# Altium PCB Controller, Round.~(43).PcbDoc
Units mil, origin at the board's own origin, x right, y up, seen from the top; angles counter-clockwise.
Board outline 1800 x 1800 mil, 4 copper layers (Top Layer, MidLayer1, MidLayer2, Bottom Layer); 55 components, 57 nets, 233 pads, 111 vias.
Unrouted connection lines stored in the file: 24.
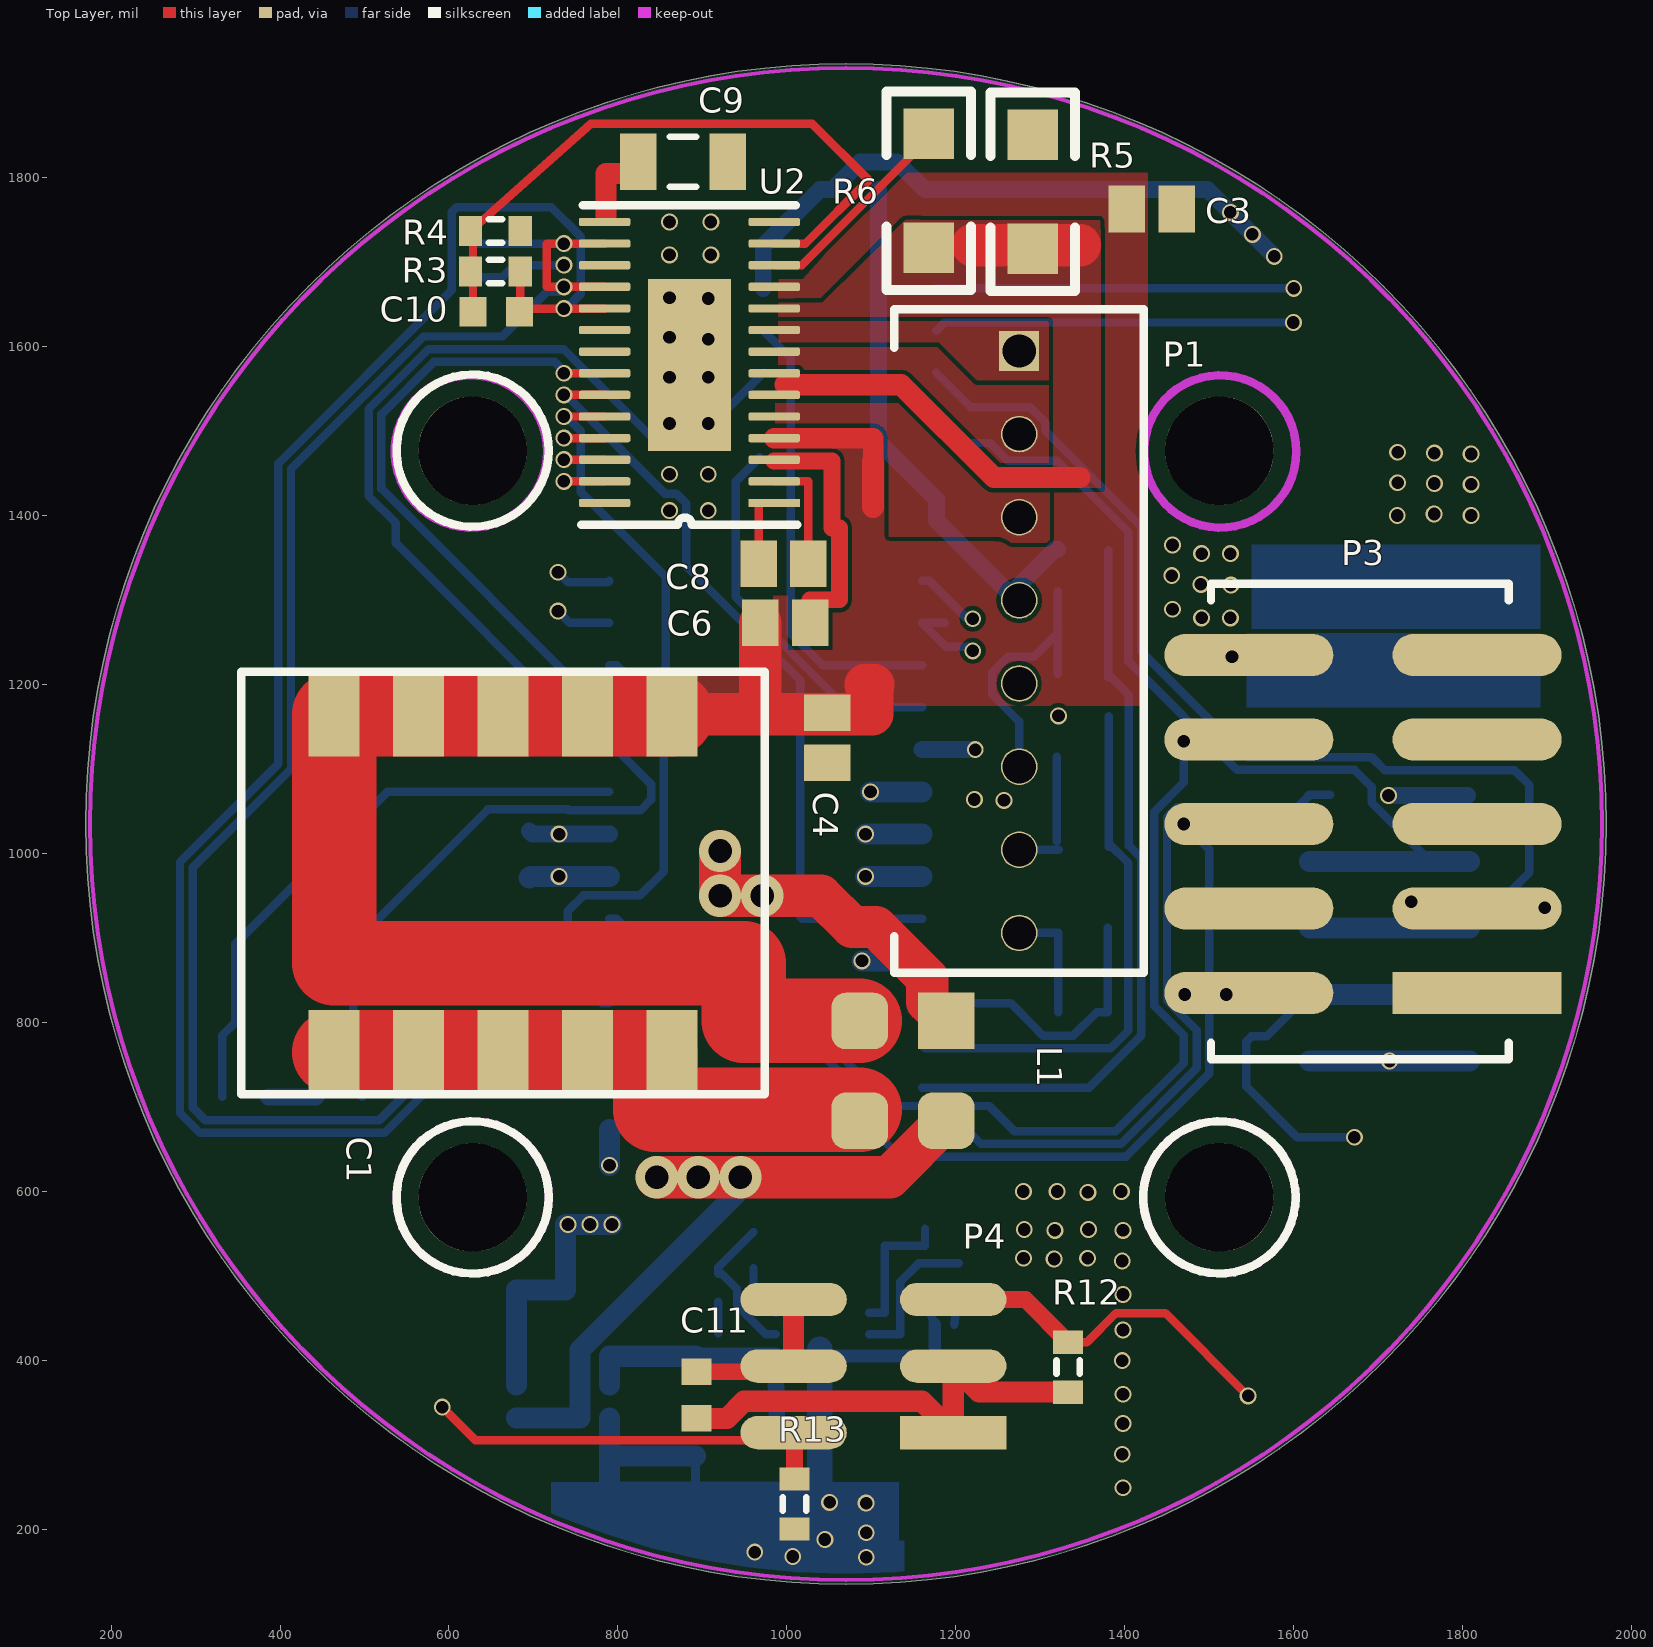
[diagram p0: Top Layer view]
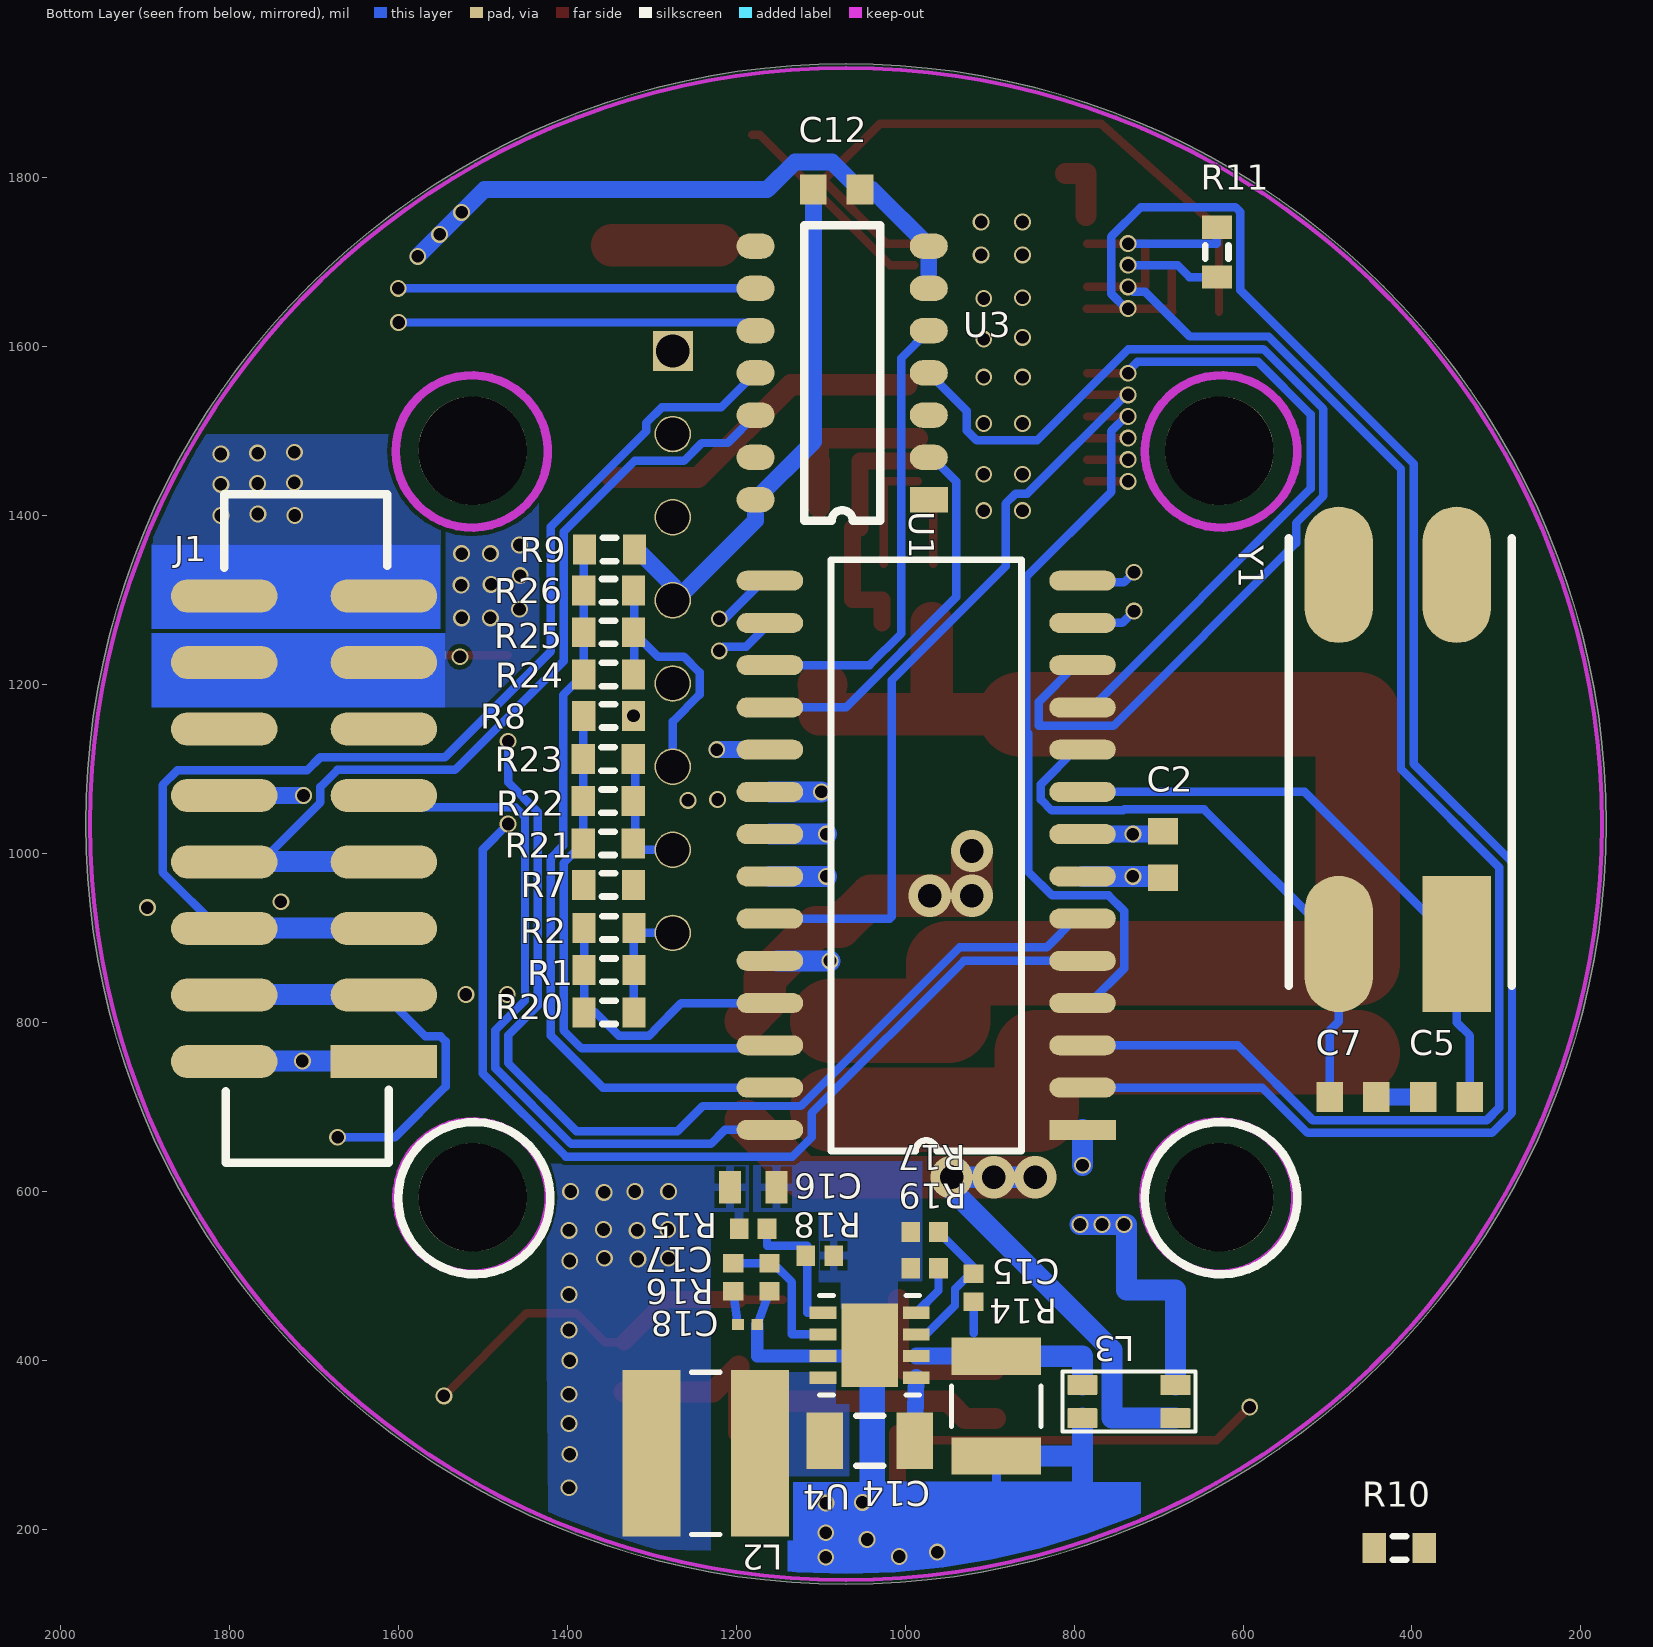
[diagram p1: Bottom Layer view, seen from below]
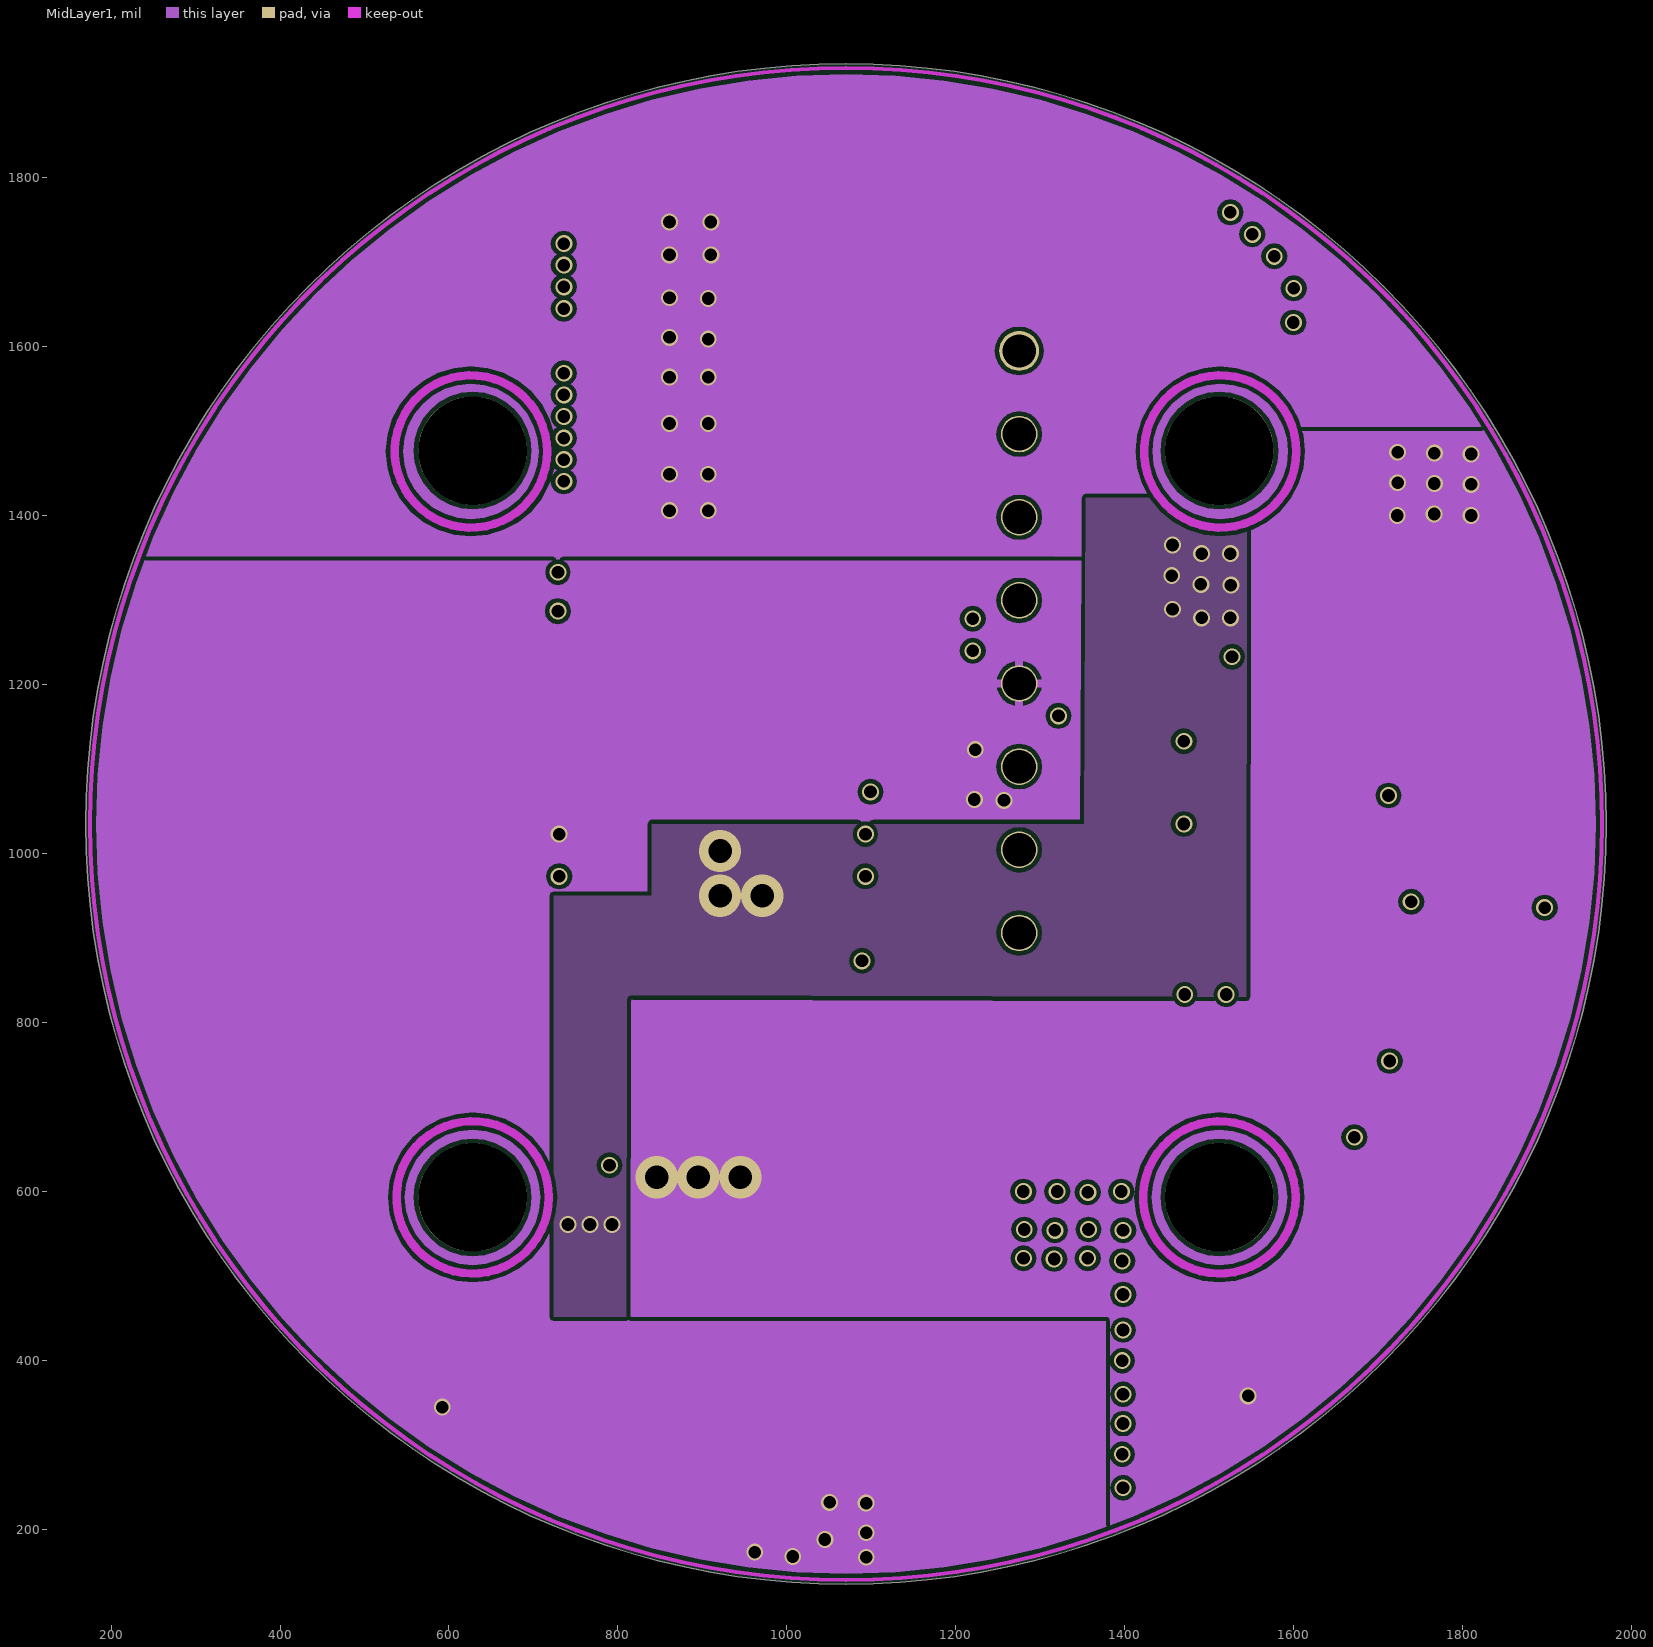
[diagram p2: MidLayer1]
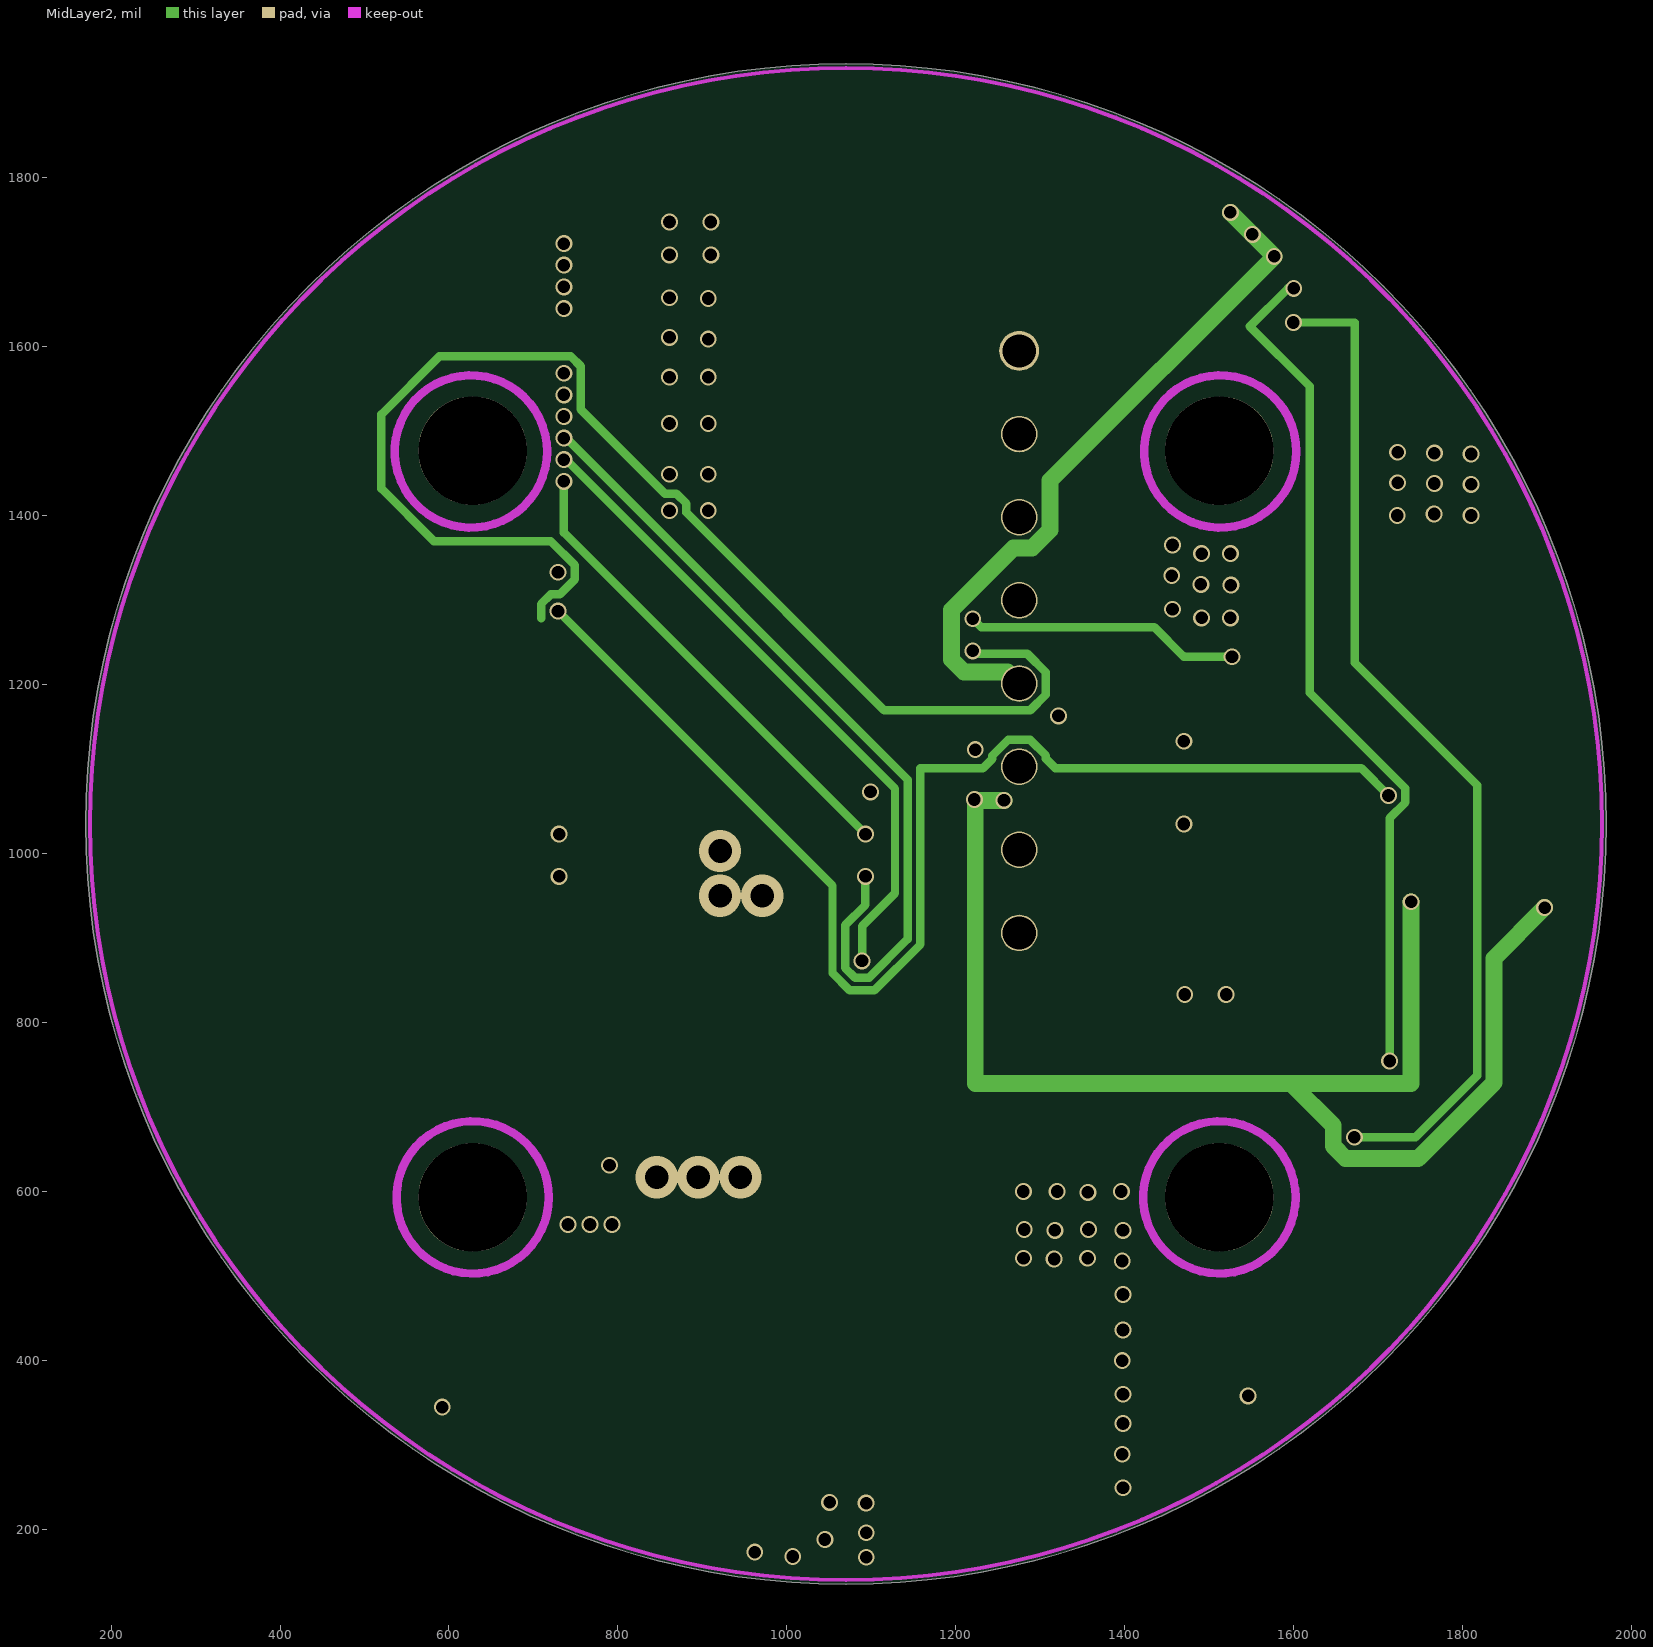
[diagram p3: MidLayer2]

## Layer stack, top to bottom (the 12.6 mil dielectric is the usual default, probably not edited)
Top Layer: signal copper 1.4
Dielectric: core 12.6, FR-4, Dk 4.8
MidLayer1: signal copper 1.4
Dielectric: prepreg 12.6, FR-4, Dk 4.8
MidLayer2: signal copper 1.4
Dielectric: core 12.6, FR-4, Dk 4.8
Bottom Layer: signal copper 1.4

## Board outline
1070,135 cw(c1070,1035) 170,1035 cw(c1070,1035) 1070,1935 cw(c1070,1035) 1970,1035 cw(c1070,1035)

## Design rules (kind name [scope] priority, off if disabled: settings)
Clearance [All] p1: gap=5
HoleSize [All] p1: absolutevalues=TRUE maxlimit=130 minlimit=15 maxpercent=80.000 minpercent=20.000
MinimumSolderMaskSliver [All] p1: minsoldermaskwidth=5
PolygonConnect PolygonConnect_Via [IsVia] p1: connectstyle=Direct reliefconductorwidth=10 reliefentries=4 polygonreliefangle="90 Angle"
PolygonConnect PolygonConnect_7 [InComponent('U2') vs InNet('GND')] p2: connectstyle=Relief reliefconductorwidth=10 reliefentries=4 polygonreliefangle="90 Angle"
PolygonConnect PolygonConnect_6 [InComponent('L1') vs InNet('GND')] p3: connectstyle=NoConnect reliefconductorwidth=10 reliefentries=4 polygonreliefangle="90 Angle"
PolygonConnect PolygonConnect_5 [InComponent('L2') vs InNet('VCC')] p4: connectstyle=Direct reliefconductorwidth=10 reliefentries=4 polygonreliefangle="90 Angle"
PolygonConnect PolygonConnect_4 [(InComponent('R19') OR InComponent('R17') OR InComponent('U4')) vs InNet('SGND')] p5: connectstyle=Direct reliefconductorwidth=10 reliefentries=4 polygonreliefangle="90 Angle"
PolygonConnect PolygonConnect_3 [All vs InNet('NetC14_1')] p6: connectstyle=Direct reliefconductorwidth=10 reliefentries=4 polygonreliefangle="90 Angle"
PolygonConnect PolygonConnect_2 [InComponent('C4')] p7: connectstyle=Relief reliefconductorwidth=10 reliefentries=4 polygonreliefangle="90 Angle"
PolygonConnect PolygonConnect_1 [(InComponent('C1')) vs InNet('GND')] p8: connectstyle=NoConnect reliefconductorwidth=10 reliefentries=4 polygonreliefangle="90 Angle"
PolygonConnect [(InNet('NetP1_1') OR InNet('NetP1_2') OR InNet('NetP1_3') OR InNet('VM') OR InNet('VSENSE')) vs (InNet('NetP1_1') OR InNet('NetP1_2') OR InNet('NetP1_3') OR InNet('VM') OR InNet('VSENSE'))] p9: connectstyle=Direct reliefconductorwidth=10 reliefentries=4 polygonreliefangle="90 Angle"
RoomDefinition Controller [InComponentClass('Controller')] p1 off: confinementstyle=ConfineIn formatcopy=TRUE lockcomponents=FALSE outline -1845,-1985 155,-1985 155,-985 -1845,-985
RoutingVias RoutingVias_1 [(InNet('ADDR_IN') OR InNet('ADDR_OUT'))] p1: holewidth=15 width=20 viastyle="Through Hole" minholewidth=15 minwidth=20 maxholewidth=15 maxwidth=20
RoutingVias [All] p2: holewidth=15 width=20 viastyle="Through Hole" minholewidth=15 minwidth=20 maxholewidth=28 maxwidth=50
SilkscreenOverComponentPads [All] p1: minsilkscreentomaskgap=10
SolderMaskExpansion [All] p1: expansion=4
Width Width_1 [All] p1: maxlimit=100 minlimit=6 preferedwidth=10
Width [InNet('VM')] p2: maxlimit=100 minlimit=20 preferedwidth=40
25 further rules are at their usual default settings.

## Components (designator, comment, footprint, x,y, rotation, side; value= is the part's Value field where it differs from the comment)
C1 "Cap Pol1" CAPSTICK-CS4-5-SMD 464,1165 r0 top
C2 "Cap Semi" 1608[0603] 695,999 r90 bottom
C3 "Cap Semi" C0805 1432,1763 r180 top
C4 "Cap Semi" C0805 1048,1137 r90 top
C5 "Cap Semi" 1608[0603] 359,712 r180 bottom
C6 "Cap Semi" C0805 998,1273 r180 top
C7 "Cap Semi" 1608[0603] 470,712 r0 bottom
C8 "Cap Semi" C0805 996,1343 r180 top
C9 "Cap Semi" C1206 877,1819 r180 top
C10 "Cap Semi" 1608[0603] 656,1641.38 r180 top locked
C11 "Cap Semi" 1608[0603] 893,359 r270 top
C12 "Cap Semi" 1608[0603] 1081,1786 r180 bottom
C14 "C1005X7R1E103K" C1206 1042,305 r180 bottom
C15 "C3225X7R2A225K230AB" 1210 892,346 r270 bottom
C16 "C1608X5R0J106M" 0603 1180,605 r180 bottom
C17 "C0402C330J5GAC" 0402 1160.5,498.5 r270 bottom
C18 "GRM033R61A472KA01D" 0201 1186.5,442.5 r180 bottom
J1 "M80-8281642" M80-828XXXXDIL 1806,1305 r180 bottom
L1 "DLW5BTM501SQ2" DLW5A_5B 1086.3,801.85 r0 top locked
L2 "LPS5030-823MLB" LPS5030 1236,290 r180 bottom
L3 "SRF3216-222Y" SRF3216 680,371 r270 bottom
P1 "MKS 1658-6-0-808" MKS_1658_A_KF 1275,1595 r270 top locked
P3 "N2510-6V0C-RB-WD" N2510_SMD 1817,835 r180 top
P4 "M80-8280642" M8082806DIL 1008,472 r0 top locked
R1 "Res3" J1-0603 1350.53,912 r0 bottom
R2 "Res3" J1-0603 1350.53,862 r0 bottom
R3 "Res3" J1-0603 655,1689 r0 top locked
R4 "Res3" J1-0603 655,1737 r180 top locked
R5 "Res3" 1206 1291,1851 r270 top locked
R6 "Res3" 1206 1168,1717 r90 top locked
R7 "Res3" J1-0603 1351,963 r180 bottom
R8 "Res3" J1-0603 1351,1163 r180 bottom
R9 "Res3" J1-0603 1350,1360 r180 bottom
R10 "Res3" J1-0603 415,178 r180 bottom
R11 "Res3" J1-0603 631,1712 r90 bottom
R12 "Res3" J1-0603 1333,392 r90 top
R13 "Res3" J1-0603 1009,230 r90 top
R14 "CRCW0402665KFKED" 0402 919,486 r90 bottom
R15 "CRCW040253K6FKED" 0402 1180,556 r180 bottom
R16 "CRCW040246K4FKED" 0402 1203.5,498.5 r90 bottom
R17 "CRCW040242K2FKED" 0402 977,552 r0 bottom
R18 "CRCW040210K0FKED" 0402 1101,524 r180 bottom
R19 "CRCW040280K6FKED" 0402 977,509 r0 bottom
R20 "Res3" J1-0603 1350.53,812 r0 bottom
R21 "Res3" J1-0603 1351.53,1012 r0 bottom
R22 "Res3" J1-0603 1351.53,1062 r0 bottom
R23 "Res3" J1-0603 1351.53,1112 r0 bottom
R24 "Res3" J1-0603 1351,1212 r0 bottom
R25 "Res3" J1-0603 1351,1262 r0 bottom
R26 "Res3" J1-0603 1351,1311.3 r0 bottom
U1 "PIC_SERVO_SC" SOP28 790,673 r0 bottom
U2 "DRV8313" HTSSOP28 985,1415 r180 top locked
U3 "LTC2864xSOP" SOP14 972,1419 r0 bottom
U4 "TPS54061DRBR" S-PVSON-N8 1042,418 r0 bottom
Y1 "MA-506 10.0000M-C0" MA506 347,893 r0 bottom

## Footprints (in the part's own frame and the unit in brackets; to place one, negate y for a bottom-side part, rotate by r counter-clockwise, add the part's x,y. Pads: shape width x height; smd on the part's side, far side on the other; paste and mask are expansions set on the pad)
0201 [mil]
  rect 14x13 smd: 1(-11.5,0) 2(11.5,0)
0402 [mil]
  rect 22x24 smd: 1(-16.5,0) 2(16.5,0)
0603 [mil]
  rect 26x38 smd: 1(-27.5,0) 2(27.5,0)
1206 [mil]
  rect 60x60 smd: 1(0,0) 2(135,0)
  silkscreen extent -50,-50 185,50
1210 [mil]
  rect 44x106 smd: 1(-59,0) 2(59,0)
  silkscreen extent -24,-53 24,53
1608[0603] [mm] "Chip Capacitor, Body 1.6x0.8mm, IPC High Density"
  rect 0.8x0.9 smd: 1(-0.7,0) 2(0.7,0)
  body extent -0.87,-0.48 0.87,0.48, height 1.3
C0805 [mm] "Chip Capacitor, Body 2.0x1.3mm, IPC High Density"
  rect 1.1x1.4 smd: 1(-0.75,0) 2(0.75,0)
  body extent -1.1,-0.72 1.1,0.72, height 1.4
C1206 [mm] "Chip Capacitor, Body 3.2x1.6mm, IPC High Density"
  rect 1.1x1.7 smd: 1(-1.35,0) 2(1.35,0)
  silkscreen extent -0.4,-0.75 0.4,0.75, body extent -1.7,-0.9 1.7,0.9, height 1.3
CAPSTICK-CS4-5-SMD [mil]
  rect 60x100 smd: 1(0,0) 1(100,0) 1(200,0) 1(300,0) 1(400,0) 2(0,-400) 2(100,-400) 2(200,-400) 2(300,-400) 2(400,-400)
  silkscreen extent -110,-450 510,50
DLW5A_5B [mm]
  rect 1.7x1.7 smd: 1(2.6,0)
  rrect50% 1.7x1.7 smd: 2(0,0) 3(0,-3) 4(2.6,-3)
HTSSOP28 [mm] "HTTSSOP 28 Pin Package, TI"
  rect 1.55x0.25 smd: 1(0,0)
  rrect50% 1.55x0.25 smd: 2(0,-0.65) 3(0,-1.3) 4(0,-1.95) 5(0,-2.6) 6(0,-3.25) 7(0,-3.9) 8(0,-4.55) 9(0,-5.2) 10(0,-5.85) 11(0,-6.5) 12(0,-7.15) 13(0,-7.8) 14(0,-8.45) 15(5.1,-8.45) 16(5.1,-7.8) 17(5.1,-7.15) 18(5.1,-6.5) 19(5.1,-5.85) 20(5.1,-5.2) 21(5.1,-4.55) 22(5.1,-3.9) 23(5.1,-3.25) 24(5.1,-2.6) 25(5.1,-1.95) 26(5.1,-1.3) 27(5.1,-0.65) 28(5.1,0)
  rect 2.5x5.18 smd: Pad(2.55,-4.15)
  silkscreen extent -0.7,-8.95 5.8,0.65
J1-0603 [mm] "Chip Resistor, Body 1.6x0.8mm, IPC High Density"
  rect 0.7x0.9 smd: 1(-0.75,0) 2(0.75,0)
  silkscreen extent -0.2,-0.35 0.2,0.35, body extent -0.85,-0.48 0.85,0.48, height 0.9
LPS5030 [mil]
  rect 68.5x197 smd: 1(-64.25,0) 2(64.25,0)
  silkscreen extent -17,-96 17,96
M80-828XXXXDIL [mm]
  rect 3.2x1 smd: 1(4.8,-14)
  oval 3.2x1 smd: 2(0,-14) 3(4.8,-12) 4(0,-12) 5(4.8,-10) 6(0,-10) 7(4.8,-8) 8(0,-8) 9(4.8,-6) 10(0,-6) 11(4.8,-4) 12(0,-4) 13(4.8,-2) 14(0,-2) 15(4.8,0) 16(0,0)
  silkscreen extent 0,-17.05 4.95,3.05
M8082806DIL [mm] "Harwin 2x3"
  rect 3.2x1 smd: 1(4.8,-4)
  oval 3.2x1 smd: 2(0,-4) 3(4.8,-2) 4(0,-2) 5(4.8,0) 6(0,0)
MA506 [mm]
  rect 2.05x4.1 smd: 1(0,0)
  oval 2.05x4.1 smd: 2(0,-11.1) 3(3.55,-11.1) 4(3.55,0)
  round 0.9 on Bottom Overlay: ""(-0.2,3.15)
  silkscreen extent -1.65,-12.2 5.05,1.26
MKS_1658_A_KF [mm] "Stocko MKS-1658 Shrouded Header Connector"
  rect 1.2x1.2 / inner round 1.2 / far side rect 1.2x1.2 hole 1: 1(0,0)
  round 1.1 hole 1: 2(2.5,0) 3(5,0) 4(7.5,0) 5(10,0) 6(12.5,0) 7(15,0) 8(17.5,0)
  silkscreen extent -1.25,-3.75 18.7,3.75
N2510_SMD [mil]
  rect 200x50 smd: 1(0,0)
  oval 200x50 smd: 2(270.08,0) 3(0,-100) 4(270.08,-100) 5(0,-200) 6(270.08,-200) 7(0,-300) 8(270.08,-300) 9(0,-400) 10(270.08,-400)
  silkscreen extent -37,-484 315,79
S-PVSON-N8 [mm]
  rect 0.805x0.37 smd: 1(-1.402,0.975) 2(-1.402,0.325) 3(-1.402,-0.325) 4(-1.402,-0.975) 5(1.402,-0.975) 6(1.402,-0.325) 7(1.402,0.325) 8(1.402,0.975)
  rect 1.702x2.5 smd paste-1.237: 9(0,0)
  silkscreen extent -1.5,-1.5 1.5,1.5
SOP14 [mil]
  rect 45x30 smd: 1(0,0)
  oval 45x30 smd: 2(0,-50) 3(0,-100) 4(0,-150) 5(0,-200) 6(0,-250) 7(0,-300) 8(205,-300) 9(205,-250) 10(205,-200) 11(205,-150) 12(205,-100) 13(205,-50) 14(205,0)
  silkscreen extent 58,-325 148,25
SOP28 [mm]
  rect 2x0.6 smd: 1(0,0)
  oval 2x0.6 smd: 2(0,-1.27) 3(0,-2.54) 4(0,-3.81) 5(0,-5.08) 6(0,-6.35) 7(0,-7.62) 8(0,-8.89) 9(0,-10.16) 10(0,-11.43) 11(0,-12.7) 12(0,-13.97) 13(0,-15.24) 14(0,-16.51) 15(9.4,-16.51) 16(9.4,-15.24) 17(9.4,-13.97) 18(9.4,-12.7) 19(9.4,-11.43) 20(9.4,-10.16) 21(9.4,-8.89) 22(9.4,-7.62) 23(9.4,-6.35) 24(9.4,-5.08) 25(9.4,-3.81) 26(9.4,-2.54) 27(9.4,-1.27) 28(9.4,0)
  silkscreen extent 1.83,-17.14 7.56,0.64
SRF3216 [mm]
  rect 0.6x0.9 smd: 1(0,0)
  rrect10% 0.6x0.9 smd: 2(0,-2.8) 3(1,-2.8) 4(1,0)
  silkscreen extent -0.4,-3.4 1.4,0.6

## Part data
C1: "Polarized Capacitor (Radial)"
C2 C3 C4 C5 C6 C7 C8 C9 C10 C11 C12: "Capacitor (Semiconductor SIM Model)"
C15: "C3225X7R2A225K23"
C18: "GRM033R61A472KA0"
L1 L3: library part "COMMON MODE CHOKE"
P1: library part "Header 8"
P3: library part "Header 5X2", "Header, 5-Pin, Dual row"
P4: library part "Header 6", "Header, 6-Pin"
R1 R2 R3 R4 R5 R6 R7 R8 R9 R10 R11 R12 R13 R20 R21 R22 R23 R24 R25 R26: "Resistor"
U4: "Imported"
Y1: library part MA-406/MA-505/MA-506

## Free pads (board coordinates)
  round 128.5 hole 128.5: ""(628,593) ""(628,1477) ""(1512,593) ""(1512,1477)

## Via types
v1: diameter 20, hole 15, Top Layer to Bottom Layer, 97 vias
v2: diameter 20, hole 15, Top Layer to Bottom Layer, tented top, 8 vias
v3: diameter 50, hole 28, Top Layer to Bottom Layer, 6 vias

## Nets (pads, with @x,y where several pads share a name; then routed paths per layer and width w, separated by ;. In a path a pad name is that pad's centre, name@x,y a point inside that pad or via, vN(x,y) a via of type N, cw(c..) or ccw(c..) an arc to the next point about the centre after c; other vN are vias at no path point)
\ENC_A: P3.5
\ENC_B: P3.7
\ENC_INDEX: P3.9
\FAULT: R11.2 U1.3 U2.16 U2.18 | length 2056.7
  Top Layer w10: U2.18 v1(736,1670.91) 716,1670.91 716,1722.09 U2.16
  Bottom Layer w10: R11.2 631,1722 v1(736,1722) ; v1@730.09,1665 716,1665 663.06,1612.06 569.64,1612.06 413,1455.41 413,1100.06 296.65,983.71 296.65,699.19 311.55,684.28 517.45,684.28 606.17,773 U1.3
ADDR_IN: J1.9 U1.28 | length 911.6
  Bottom Layer w10: U1.28 1213.28,673 1230,656.28 1395.4,656.28 1485,745.88 1485,790.95 1450,825.95 1450,1043.28 1461.72,1055 1604.57,1055 1619.02,1069.45 1643.45,1069.45 J1.9
ADDR_OUT: J1.10 U1.13 | length 1667
  MidLayer2 w10: v1(729,1287) 1054,962 1054,858.5 1074.5,838 1103.5,838 1158,892.5 1158,1101 1232.11,1101 1243.35,1112.24 1243.35,1115.99 1261.89,1134.53 1288.11,1134.53 1306.65,1115.99 1306.65,1112.24 1317.89,1101 1680,1101 v1(1712.22,1068.78)
  Bottom Layer w10: v1(729,1287) 743,1273 U1.13
  Bottom Layer w20: v1(1712.22,1068.78) J1.10
CUR_SENSE: C10.1 R3.2 U1.2 U2.19 | length 2153
  Top Layer w10: C10.1 C10.1@684.62,1641.38 ; C10.1@684.53,1641.38 R3.2 ; C10.1@685.41,1645 v1(736,1645) U2.19@785,1645
  Bottom Layer w10: v1(736,1645) 738.38,1645 756,1662.62 756,1730.28 720.98,1765.31 609.14,1765.31 603.28,1759.45 603.28,1666.91 398,1461.63 398,1106.28 281.65,989.92 281.65,692.98 305.34,669.28 523.66,669.28 577.38,723 U1.2
ENC_A: P3.6 U1.5 | length 1171.4
  Bottom Layer w10: U1.5 930.46,873 1110.71,692.75 1110.71,663.97 1133.39,641.28 1401.62,641.28 1500,739.67 1500,1005 v1(1470,1035)
ENC_B: P3.8 U1.6 | length 1227.6
  Bottom Layer w10: U1.6 798.4,923 832.4,889 935.67,889 1123.48,701.19 1239.53,701.19 1269.44,671.28 1389.19,671.28 1470,752.09 1470,784.73 1435,819.73 1435,1049.5 1470,1084.5 v1(1470,1133)
ENC_INDEX: P3.10 U1.15 | length 479.3
  Top Layer w10: P3.10@1470.43,1235 P3.10
  MidLayer2 w10: v1(1220,1278) 1229.93,1268.07 1434.93,1268.07 1469,1234 ; 1470,1233 v1(1527,1233)
  Bottom Layer w10: U1.15 1168.48,1323 1213.48,1278 v1(1220,1278)
GND: C1.2 C3.1 C4.1 C9.1 L1.3 R4.1 R5.1 R10.1 U2.14 U2.20 U2.28 U2.Pad | length 690.5
  Top Layer w100: C1.2@464,765 564,765 664,765 764,765 844,765 844,696.85 L1.3@1086.3,696.85
  other v1: 861,1406 907,1406 861,1449 907,1449 861,1509 907,1509 861,1564 907,1564 907,1609 861,1611 907,1657 861,1658 861,1708.68 910,1708.68 861,1747.68 910,1747.68
HALL1: P1.8 R1.1 R2.1 R20.1 | length 142
  Bottom Layer w10: P1.8@1275,904 P1.8 1321,906.02 R2.1 R20.1
HALL2: P1.7 R21.1 R22.1 R23.1 | length 163.7
  Bottom Layer w10: P1.7@1258.35,1004.45 P1.7 R21.1@1322,1004.45 ; R21.1@1319.55,1014.45 R23.1@1319.55,1114.45
HALL3: P1.6 R24.1 R25.1 R26.1 | length 320
  Bottom Layer w10: P1.6 1275,1156.53 1243.35,1188.19 1243.35,1214.41 1261.89,1232.95 1292.43,1232.95 R25.1@1320.6,1261.13 ; R24.1@1320.6,1212.87 R25.1@1320.6,1261.13 ; R26.1@1320.6,1310.43 R25.1@1320.6,1261.13 ; R25.1 R25.1@1320.6,1261.13
LIMIT1: P4.2 R13.2 U1.16 | length 2181.1
  Top Layer w10: v1(592,344.77) 631.08,305.69 999.17,305.69 P4.2
  Top Layer w20: R13.2 P4.2@1009,313.52
  MidLayer2 w10: 709,1278.72 709,1295.28 720.72,1307 731.28,1307 749,1324.72 749,1341.28 720.34,1369.94 582.07,1369.94 519.94,1432.07 519.94,1519.93 588.56,1588.54 744.28,1588.54 756,1576.83 756,1525.72 855.72,1426 869.28,1426 881,1414.28 881,1403.72 1115.07,1169.65 1288.11,1169.65 1306.65,1188.19 1306.65,1214.41 1284.6,1236.46 v1@1223.54,1236.46
  Bottom Layer w10: U1.16@1187,1273 U1.16 1188.27,1244.81 1215.19,1244.81 v1(1220,1240)
LIMIT2: P4.5 R12.2 U1.14 | length 543.6
  Top Layer w10: P4.5@1145,472 P4.5 ; R12.2 1355.24,421.53 1389.72,456 1448,456 v1(1546,358)
  Top Layer w20: P4.5 1282.53,472 R12.2
  Bottom Layer w10: v1(729,1333) 741,1321 788,1321 U1.14
NetC5_2: C5.2 U1.9 Y1.1 | length 705
  Bottom Layer w10: C5.2 331.44,784.44 347,800 Y1.1 527,1073 U1.9
NetC6_1: C6.1 U2.3 | length 303.6
  Top Layer w20: U2.3@985,1464.77 1053.39,1464.77 1053.39,1385.56 1062.18,1385.56 1062.18,1300.44 1027.53,1300.44 C6.1
NetC7_2: C7.2 U1.10 Y1.4 | length 694.2
  Bottom Layer w10: C7.2 497.56,790.44 486.76,801.24 Y1.4 646.07,1052.31 740.63,1052.31 741.75,1051.19 826.59,1051.19 839.37,1063.97 839.37,1082.03 798.4,1123 U1.10
NetC8_1: C8.1 U2.2 | length 138.1
  Top Layer w10: U2.2 1025.53,1440.59 C8.1
NetC8_2: C8.2 U2.1 | length 72
  Top Layer w10: C8.2 U2.1@966.47,1415
NetC9_2: C9.2 U2.15 | length 73.4
  Top Layer w25: 785.85,1755.57 785.85,1805 C9.2@809.85,1805
NetC10_2: C10.2 R3.1 R4.2 U2.13 | length 792.5
  Top Layer w10: R4.2@625.47,1743.47 R4.2 768.05,1863.95 1029.96,1863.95 1096.91,1797 1022,1722.09 U2.13 ; C10.2 R4.2@628.44,1737
NetC14_1: C14.1 L2.2 U4.8
NetC14_2: C14.2 U4.1 | length 74.6
  Bottom Layer w20: U4.1 C14.2
NetC15_1: C15.1 L3.2 R14.1 U4.2 | length 267.8
  Bottom Layer w10: 919,432 R14.1
  Bottom Layer w20: C15.1@892.2,405.2 U4.2
  Bottom Layer w25: L3.2 790.24,405 C15.1
NetC17_1: C17.1 R16.2 U4.6 | length 177.4
  Bottom Layer w10: U4.6 1134,430.8 1134,492.64 1156.36,515 C17.1 R16.2
NetC18_1: C18.1 R16.1 | length 39.9
  Bottom Layer w10: C18.1 R16.1
NetJ1_13: J1.13 J1.14 L1.1 L3.1 | length 701.5
  Top Layer w50: v3(921,1003) v3(921,950) 1040.51,950 1077.51,913 1105.57,913 1166.3,852.27 1166.3,824.21 L1.1
  Bottom Layer w25: L3.1 680,483.25 737.75,483.25 737.75,561 v1(741,561) v1(767,561) v1(793,561)
  other v1: 1525,1279 1525.58,1317.71 1490,1318.73 1455.57,1329 1491,1355 1525,1355 1456.57,1365.27
  other v2: 1491,1279 1456.57,1289.27
  other v3: 971,950
NetJ1_15: J1.15 J1.16 L1.4 L3.4 | length 908.3
  Top Layer w50: v3(846,616.85) v3(895,616.85) v3(945,616.85) 1121.77,616.85 L1.4
  Bottom Layer w25: L3.4 755.02,331.63 755.02,412.21 945,602.19 v3(945,616.85) v3(895,616.85) v3(846,616.85)
  other v1: 1722.5,1400.27 1810,1400.27 1766.25,1402 1810,1437 1766.5,1438 1723,1439 1810,1473 1766.5,1474 1723,1475
NetP1_1: P1.1 U2.9
NetP1_2: P1.2 U2.8
NetP1_3: P1.3 U2.5
NetR1_2: R1.2 R2.2 R7.1 R20.2 U1.25 | length 347.9
  Bottom Layer w10: U1.25 1265,823 1297.22,790.78 1297.22,790.14 1303.08,784.28 1338.92,784.28 1366.64,812 R20.2 R2.2 R1.2
NetR6_2: R6.2 U2.12 | length 256.1
  Top Layer w10: U2.12@988.94,1696.5 1017.92,1696.5 1172.42,1851 R6.2@1181,1851
NetR8_1: R8.1 R21.2 R22.2 R23.2 U1.26 | length 640
  Bottom Layer w10: U1.26 1163.79,769.28 1382.98,769.28 1404.31,790.61 1404.31,988.75 R21.2 ; R21.2@1381.06,1008.11 R21.2 ; R8.1@1381.06,1162.47 R23.2 R22.2 R21.2
NetR9_1: R9.1 R24.2 R25.2 R26.2 U1.27 | length 878.7
  Bottom Layer w10: U1.27 1357.91,723 1419.31,784.4 1419.31,994.96 1404.83,1009.43 1404.83,1187.69 R24.2 ; R24.2@1380.53,1208.64 R24.2 ; R9.1@1380.53,1359 R26.2 R25.2 R24.2
NetR14_2: R14.2 R17.1 U4.3 | length 175.7
  Bottom Layer w10: R17.1 919,510.5 R14.2 923.14,502.5 941,484.64 941,464.91 975.11,430.8 U4.3
NetR15_2: R15.2 R18.1 U4.5 | length 165.9
  Bottom Layer w10: U4.5 1116,456.39 1116,536 1163.5,536 R15.2
NetR19_1: R19.1 U4.4 | length 63.5
  Bottom Layer w10: R19.1 960.5,482.67 U4.4
NetU1_4: U1.4 U2.24 | length 904.4
  Top Layer w10: v1(736,1517.36) U2.24
  Bottom Layer w10: v1@738.69,1517.36 756,1500.06 756,1428.18 856.81,1327.37 856.81,1144.98 854,1142.16 854,1088.62 854.37,1088.25 854.37,978.97 825.9,950.5 759.1,950.5 740.63,932.03 740.63,863.97 781.6,823 U1.4
NetU1_11: U1.11 U2.22 | length 755.2
  Top Layer w10: v1(736,1568.54) U2.22
  Bottom Layer w10: v1(736,1568.54) 738.69,1568.54 725.18,1582.06 582.07,1582.06 519.94,1519.93 519.94,1432.07 U1.11@779.01,1173
NetU1_12: U1.12 U3.4 | length 1252.4
  Bottom Layer w10: U1.12 798.4,1223 841.81,1179.59 841.81,1151.19 753.41,1151.19 537.12,1367.48 537.12,1391.22 504.94,1423.39 504.94,1526.14 575.86,1597.06 735.77,1597.06 843.83,1489 915.28,1489 927,1500.72 927,1524 U3.4
NetU1_17: U1.17 U3.5 | length 543.1
  Bottom Layer w10: U3.5 1004.5,1586.5 1004.5,1260.5 1042,1223 U1.17
NetU1_18: U1.18 U3.2 | length 451.9
  Bottom Layer w10: U3.2@967.86,1469 939.5,1440.64 939.5,1303.5 1070,1173 U1.18
NetU1_21: U1.21 U2.27 | length 680.8
  Top Layer w10: v1(736,1440.59) U2.27
  MidLayer2 w10: v1(736,1440.59) 736,1380 v1(1093,1023)
  Bottom Layer w25: v1(1093,1023) U1.21
NetU1_22: U1.22 U2.25 | length 1091.8
  Top Layer w10: v1(736,1491.77) U2.25
  MidLayer2 w10: v1@738.84,1491.77 1143,1087.61 1143,898.72 1097.28,853 1080.72,853 1069,864.72 1069,915.21 1093,939.21 v1(1093,973)
  Bottom Layer w25: v1(1093,973) U1.22
NetU1_23: U1.23 U2.23 | length 936.6
  Top Layer w10: v1(736,1542.95) U2.23
  Bottom Layer w10: v1(736,1542.95) 738.69,1542.95 855.65,1426 869.28,1426 881,1414.28 881,1340 1016,1205 1016,925 1018,923 U1.23
NetU1_24: U1.24 U2.26 | length 895.2
  Top Layer w10: v1(736,1466.33) U2.26
  MidLayer2 w10: v1(736,1466.33) 738.55,1466.33 1128,1076.87 1128,953 1089,914 v1(1089,873)
  Bottom Layer w10: v1(736,1466.33) v1@738.55,1466.33 ; U1.24@1151.67,873 U1.24
  Bottom Layer w25: v1(1089,873) U1.24@1151.67,873
RS422_RX_A: J1.7 J1.8 U3.12 | length 1144.1
  Bottom Layer w10: U3.12 1210,1486 1240.81,1486 1261.89,1464.92 1320.25,1464.92 1404.31,1380.86 1404.31,1337.14 1404.31,1227.69 1533,1099 1672.09,1099 1692.22,1078.87 1692.22,1060.5 1762,990.71 1762.68,990.04 J1.8 ; J1.7@1612.48,990.71 J1.7@1619.02,990.71
  Bottom Layer w25: J1.7@1619.02,990.71 1762,990.71 J1.8@1808,990.71
RS422_RX_B: J1.5 J1.6 U3.11 | length 1395.7
  Bottom Layer w10: U3.11 1217.77,1528.23 1288.11,1528.23 1306.65,1509.69 1306.65,1499.73 1419.31,1387.07 1419.31,1239.55 1544.86,1114 1692.38,1114 1707.92,1098.46 1861.6,1098.46 1878.99,1081.08 1878.99,977.74 1812.55,911.3 J1.6 ; J1.5@1612.48,911.97 J1.5@1619.02,911.97
  Bottom Layer w25: J1.5@1619.02,911.97 J1.6@1808,911.97
RS422_TX_A: J1.3 J1.4 U3.10 | length 2116.9
  MidLayer2 w10: v1(1599.62,1628.62) 1672,1628.62 1672,1226 1817,1081 1817,737 1744.16,664.16 v1(1671.84,664.16)
  Bottom Layer w10: U3.10 1186.62,1628.62 v1(1599.62,1628.62) ; J1.3 1567.97,783.5 1549.89,783.5 1544.03,777.65 1544.03,724.13 1604,664.16 v1(1671.84,664.16)
  Bottom Layer w25: J1.3@1619.02,833.23 J1.4@1808,833.23
RS422_TX_B: J1.1 J1.2 U3.9 | length 1635.7
  MidLayer2 w10: v1@1593,1669 1548,1624 1619.06,1552.94 1619.06,1190.23 1732.22,1077.06 1732.22,1060.5 1713.51,1041.79 v1(1713.51,754.49)
  Bottom Layer w10: U3.9 v1(1600,1669) ; J1.2@1808,754.49 J1.2@1814.55,754.49
  Bottom Layer w25: J1.1@1619.02,754.49 v1(1713.51,754.49) J1.2@1808,754.49
SGND: C2.2 C5.1 C7.1 C11.1 C12.2 C15.2 C16.2 C17.2 C18.2 L3.3 P1.5 P3.3 P4.4 P4.6 R10.2 R17.2 R18.2 R19.2 U1.8 U1.19 U3.6 U3.7 U4.7 U4.9 | length 4429.7
  Top Layer w20: C11.1 P4.4@1001.3,386.56
  Top Layer w25: P4.4 P4.6
  MidLayer2 w20: 1223,935 1223,728 1597,728 ; 1223,939 1223,1063 v1(1257,1063) ; P1.5 1261.3,1215 1209.64,1215 1195,1229.64 1195,1288.36 1268.14,1361.5 1290.18,1361.5 1311.65,1382.97 1311.65,1441.65 v1(1577,1707) v1(1551,1733) v1(1525,1759) ; v1(1739,943) 1739,728 1597,728 ; v1(1897,936) 1837,876 1837,728.72 1747.45,639.16 1661.48,639.16 1646.84,653.81 1646.84,678.16 1597,728
  Bottom Layer w10: C17.2 C18.2
  Bottom Layer w15: U4.9@1042,405.2 U4.7 1175,405.2 C18.2
  Bottom Layer w20: C5.1 C7.1 ; C2.2 698.56,1023 v1(730.38,1023) U1.8 ; U3.6 U3.7 1039,1786 C12.2 1053.88,1786 1086.6,1818.72 1130.52,1818.72 1163.24,1786 1498,1786 v1(1525,1759) v1(1551,1733) v1(1577,1707) ; U1.19 v1(1223,1123)
  Bottom Layer w25: L3.3 790.24,287 ; C15.2 790.24,287 ; 1042,244 790.24,244 790.24,287
  Bottom Layer w30: 1039,252 U4.9@1039,413.2
  other v1: 1094,167 1007,168 962,173 1045,188 1094,196 1093.82,231 1050.68,232 1222,1064
VCC: C2.1 C11.2 C12.1 C16.1 L2.1 P1.4 P3.2 P4.1 P4.3 R7.2 R8.2 R9.2 R11.1 R12.1 R13.1 R15.1 U1.1 U1.7 U1.20 U2.17 U3.14 | length 1486.3
  Top Layer w25: C11.2 929.03,331.44 949.29,351.7 1159.79,351.7 P4.1 P4.3 1227.76,362.47 R12.1
  Bottom Layer w10: R11.1 663.47,1682.47 677.5,1696.5 v1(736,1696.5)
  Bottom Layer w20: C12.1 1108.56,1487.44 U3.14 1177,1394.47 P1.4@1275,1296.47 ; P1.4@1275,1317.54 1317.46,1360 R9.2
  Bottom Layer w25: C2.1 696.56,973 v1(730.38,973) U1.7 ; v1(790,631) U1.1 ; v1(1099.02,1073) U1.20
  other v1: 1397,289 1398,325.27 1397,399.73 1398,436 1397,517.73 1316.34,520 1280.08,521 1317.27,554 1398,554 1281,555 1356.27,599 1280,600 1320,600 1471,833.23 1520,833.23 1321.47,1163
  other v2: 1398,249.27 1398,360 1398,478 1356.08,521 1357,555 1396,600
VM: C1.1 C3.2 C4.2 C6.2 L1.2 U2.4 U2.11 | length 1973
  Top Layer w24: U2.4 1102.18,1491.77 1102.18,1464
  Top Layer w26: 1102.18,1410 1102.18,1464
  Top Layer w50: C1.1@864,1165 968.47,1165 ; C6.2 968.47,1165 ; 1093.39,1199.77 1102.18,1199.77 ; 1101,1199.77 1101,1165 968.47,1165
  Top Layer w100: C1.1@864,1165 764,1165 664,1165 564,1165 464,1165 464,870 949,870 949,801.85 L1.2
VSENSE: R5.2 R6.1 U2.6 U2.7 U2.10 | length 521.6
  Top Layer w25: 997.92,1555 1135,1555 1245,1445 1347,1445
  Top Layer w50: 1220,1720 1347,1720
pads on no net: J1.11 J1.12 P3.1 P3.4 U2.21 U3.1 U3.3 U3.8 U3.13 Y1. Y1.2 Y1.3

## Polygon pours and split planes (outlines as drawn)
VM on Top Layer "Top Layer-No Net" (solid, pour order 131): 986,1198 984,1198 984,1305 1054,1305 1054,1487 1054,1485 1115.23,1485 1115.23,1198
VM on Top Layer "Top Layer-No Net" (solid, pour order 127): 892,1214.74 892,1180 1094,1180 1094,1214.74
NetP1_3 on Top Layer "Top Layer-No Net" (solid, pour order 66): 986,1533 1163,1533 1261,1436 1311,1436 1311,1362 1305,1356 1304,1357 1109,1357 1109,1484 1093,1509 986,1509
VM on Top Layer "Top Layer-No Net" (solid, pour order 76): 989.93,1652.03 1427,1650 1427,1806 1080,1806 1045,1771 1045,1709 1018.56,1680 990.24,1679.93
VSENSE on Top Layer "Top Layer-No Net" (solid, pour order 72): 989.78,1627 1383,1627 1384,1750 1140,1750 1042,1652 990.24,1652.03
NetP1_1 on Top Layer "Top Layer-No Net" (solid, pour order 60): 989.89,1630 1310,1630 1310,1560 1225,1560 1180,1605 990.24,1605.12
NetP1_2 on Top Layer "Top Layer-No Net" (solid, pour order 64): 989.78,1599.6 1310.61,1599.49 1309.78,1450 1243,1450 1241,1452.14 1129,1571.86 1021,1571 989.93,1570.93
VM on Top Layer "Top Layer-No Net" (solid, pour order 96): 1089.67,1433 1087.44,1174.94 1427,1174.94 1427,1650.24 1377.15,1650.24 1371.74,1433
VSENSE on Top Layer "Top Layer-No Net" (solid, pour order 78): 1315.41,1627 1371.74,1627 1371.74,1433 1366,1433 1315,1433
NetJ1_13 on Bottom Layer "Top Layer-No Net" (solid, pour order 137): 1544.03,1173 1544,1421 1434,1421 1433,1173
NetJ1_15 on Bottom Layer "Top Layer-No Net" (solid, pour order 139): 1550,1366 1550,1496.12 1549.54,1496.57 1890,1496.57 1890,1368 1892,1366
VCC on Bottom Layer "Top Layer-No Net" (solid, pour order 108): 1185,636 1185,576 1230,576 1230,175 1421.85,178 1424.33,407 1424.33,633
SGND on Bottom Layer "Top Layer-No Net" (solid, pour order 106): 1076,461 1076,492.64 1102,492.64 1102,576 1180,576 1180,636 980,636 980,494 1009,494 1009,461
NetC14_1 on Bottom Layer "Top Layer-No Net" (solid, pour order 102): 1082,386 1082,348 1066,348 1066,263 1154,263 1154,386
GND on MidLayer1 "Top Layer-No Net" (solid, pour order 153): 1316,1352 1316,1508 1430,1508 1443.75,1508 1443.75,1352
NetJ1_13 on MidLayer1 "Top Layer-No Net" (solid, pour order 145): 815,452 724,452 724,950 840.3,950 840.3,1035 1352,1035 1354,1421 1549,1421 1549,827 816,827
GND on Top Layer "Top Layer-No Net" (solid, shelved, pour order 116): 1070,140 cw(c1070,1035) 175,1035 cw(c1070,1035) 1070,1930 cw(c1070,1035) 1965,1035 cw(c1070,1035)
VCC on MidLayer2 "Top Layer-No Net" (solid, shelved, pour order 157): 1070,140 cw(c1070,1035) 175,1035 cw(c1070,1035) 1070,1930 cw(c1070,1035) 1965,1035 cw(c1070,1035)

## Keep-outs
Keep-Out Layer:
  circle w5: c1070,1035 r895
  circle w10: c626,1476 r90.15
  circle w10: c1513,1476 r90.15
  circle w10: c1512,593 r90.15
  circle w10: c628,593 r90.15

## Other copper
MidLayer1:
  region net GND: 641.61,1554.5 656.63,1549.94 670.47,1542.55 682.59,1532.59 692.55,1520.47 699.94,1506.63 704.5,1491.61 706.04,1476 704.5,1460.39 699.94,1445.37 692.55,1431.53 682.59,1419.41 670.47,1409.45 656.63,1402.06 641.61,1397.5 626,1395.96 610.39,1397.5 595.37,1402.06 581.53,1409.45 569.41,1419.41 559.45,1431.53 552.06,1445.37 547.5,1460.39 545.96,1476 547.5,1491.61 552.06,1506.63 559.45,1520.47 569.41,1532.59 581.53,1542.55 595.37,1549.94 610.39,1554.5 626,1556.04 hole: 628,1546.59 614.42,1545.25 601.37,1541.29 589.34,1534.86 578.8,1526.2 570.14,1515.66 563.71,1503.63 559.75,1490.58 558.41,1477 559.75,1463.42 563.71,1450.37 570.14,1438.34 578.8,1427.8 589.34,1419.14 601.37,1412.71 614.42,1408.75 628,1407.41 641.58,1408.75 654.63,1412.71 666.66,1419.14 677.2,1427.8 685.86,1438.34 692.29,1450.37 696.25,1463.42 697.59,1477 696.25,1490.58 692.29,1503.63 685.86,1515.66 677.2,1526.2 666.66,1534.86 654.63,1541.29 641.58,1545.25
  region net GND: 91 vertices and 10 holes, not listed, extent 241.57,1347.93 1821.89,1922.48
  region net NetJ1_15: 1527.61,671.5 1542.63,666.94 1556.47,659.55 1568.59,649.59 1578.55,637.47 1585.94,623.63 1590.5,608.61 1592.04,593 1590.5,577.39 1585.94,562.37 1578.55,548.53 1568.59,536.41 1556.47,526.45 1542.63,519.06 1527.61,514.5 1512,512.96 1496.39,514.5 1481.37,519.06 1467.53,526.45 1455.41,536.41 1445.45,548.53 1438.06,562.37 1433.5,577.39 1431.96,593 1433.5,608.61 1438.06,623.63 1445.45,637.47 1455.41,649.59 1467.53,659.55 1481.37,666.94 1496.39,671.5 1512,673.04 hole: 1512,662.59 1498.42,661.25 1485.37,657.29 1473.34,650.86 1462.8,642.2 1454.14,631.66 1447.71,619.63 1443.75,606.58 1442.41,593 1443.75,579.42 1447.71,566.37 1454.14,554.34 1462.8,543.8 1473.34,535.14 1485.37,528.71 1498.42,524.75 1512,523.41 1525.58,524.75 1538.63,528.71 1550.66,535.14 1561.2,543.8 1569.86,554.34 1576.29,566.37 1580.25,579.42 1581.59,593 1580.25,606.58 1576.29,619.63 1569.86,631.66 1561.2,642.2 1550.66,650.86 1538.63,657.29 1525.58,661.25
  region net NetJ1_15: 198 vertices and 19 holes, not listed, extent 815,205.05 1957.48,1500.82
  region net SGND: 1528.61,1554.5 1543.63,1549.94 1557.47,1542.55 1569.59,1532.59 1579.55,1520.47 1586.94,1506.63 1591.5,1491.61 1593.04,1476 1591.5,1460.39 1586.94,1445.37 1579.55,1431.53 1569.59,1419.41 1557.47,1409.45 1543.63,1402.06 1528.61,1397.5 1513,1395.96 1497.39,1397.5 1482.37,1402.06 1468.53,1409.45 1456.41,1419.41 1446.45,1431.53 1439.06,1445.37 1434.5,1460.39 1432.96,1476 1434.5,1491.61 1439.06,1506.63 1446.45,1520.47 1456.41,1532.59 1468.53,1542.55 1482.37,1549.94 1497.39,1554.5 1513,1556.04 hole: 1512,1546.59 1498.42,1545.25 1485.37,1541.29 1473.34,1534.86 1462.8,1526.2 1454.14,1515.66 1447.71,1503.63 1443.75,1490.58 1442.41,1477 1443.75,1463.42 1447.71,1450.37 1454.14,1438.34 1462.8,1427.8 1473.34,1419.14 1485.37,1412.71 1498.42,1408.75 1512,1407.41 1525.58,1408.75 1538.63,1412.71 1550.66,1419.14 1561.2,1427.8 1569.86,1438.34 1576.29,1450.37 1580.25,1463.42 1581.59,1477 1580.25,1490.58 1576.29,1503.63 1569.86,1515.66 1561.2,1526.2 1550.66,1534.86 1538.63,1541.29 1525.58,1545.25
  region net SGND: 643.61,671.5 658.63,666.94 672.47,659.55 684.59,649.59 694.55,637.47 701.94,623.63 706.5,608.61 708.04,593 706.5,577.39 701.94,562.37 694.55,548.53 684.59,536.41 672.47,526.45 658.63,519.06 643.61,514.5 628,512.96 612.39,514.5 597.37,519.06 583.53,526.45 571.41,536.41 561.45,548.53 554.06,562.37 549.5,577.39 547.96,593 549.5,608.61 554.06,623.63 561.45,637.47 571.41,649.59 583.53,659.55 597.37,666.94 612.39,671.5 628,673.04 hole: 628,662.59 614.42,661.25 601.37,657.29 589.34,650.86 578.8,642.2 570.14,631.66 563.71,619.63 559.75,606.58 558.41,593 559.75,579.42 563.71,566.37 570.14,554.34 578.8,543.8 589.34,535.14 601.37,528.71 614.42,524.75 628,523.41 641.58,524.75 654.63,528.71 666.66,535.14 677.2,543.8 685.86,554.34 692.29,566.37 696.25,579.42 697.59,593 696.25,606.58 692.29,619.63 685.86,631.66 677.2,642.2 666.66,650.86 654.63,657.29 641.58,661.25
  region net SGND: 127 vertices and 12 holes, not listed, extent 182.52,147.52 1377.94,1346.97
  region net SGND: 1528.61,1554.5 1543.63,1549.94 1557.47,1542.55 1569.59,1532.59 1579.55,1520.47 1586.94,1506.63 1591.5,1491.61 1593.04,1476 1591.5,1460.39 1586.94,1445.37 1579.55,1431.53 1569.59,1419.41 1557.47,1409.45 1543.63,1402.06 1528.61,1397.5 1513,1395.96 1497.39,1397.5 1482.37,1402.06 1468.53,1409.45 1456.41,1419.41 1446.45,1431.53 1439.06,1445.37 1434.5,1460.39 1432.96,1476 1434.5,1491.61 1439.06,1506.63 1446.45,1520.47 1456.41,1532.59 1468.53,1542.55 1482.37,1549.94 1497.39,1554.5 1513,1556.04 hole: 1512,1546.59 1498.42,1545.25 1485.37,1541.29 1473.34,1534.86 1462.8,1526.2 1454.14,1515.66 1447.71,1503.63 1443.75,1490.58 1442.41,1477 1443.75,1463.42 1447.71,1450.37 1454.14,1438.34 1462.8,1427.8 1473.34,1419.14 1485.37,1412.71 1498.42,1408.75 1512,1407.41 1525.58,1408.75 1538.63,1412.71 1550.66,1419.14 1561.2,1427.8 1569.86,1438.34 1576.29,1450.37 1580.25,1463.42 1581.59,1477 1580.25,1490.58 1576.29,1503.63 1569.86,1515.66 1561.2,1526.2 1550.66,1534.86 1538.63,1541.29 1525.58,1545.25
  region net SGND: 643.61,671.5 658.63,666.94 672.47,659.55 684.59,649.59 694.55,637.47 701.94,623.63 706.5,608.61 708.04,593 706.5,577.39 701.94,562.37 694.55,548.53 684.59,536.41 672.47,526.45 658.63,519.06 643.61,514.5 628,512.96 612.39,514.5 597.37,519.06 583.53,526.45 571.41,536.41 561.45,548.53 554.06,562.37 549.5,577.39 547.96,593 549.5,608.61 554.06,623.63 561.45,637.47 571.41,649.59 583.53,659.55 597.37,666.94 612.39,671.5 628,673.04 hole: 628,662.59 614.42,661.25 601.37,657.29 589.34,650.86 578.8,642.2 570.14,631.66 563.71,619.63 559.75,606.58 558.41,593 559.75,579.42 563.71,566.37 570.14,554.34 578.8,543.8 589.34,535.14 601.37,528.71 614.42,524.75 628,523.41 641.58,524.75 654.63,528.71 666.66,535.14 677.2,543.8 685.86,554.34 692.29,566.37 696.25,579.42 697.59,593 696.25,606.58 692.29,619.63 685.86,631.66 677.2,642.2 666.66,650.86 654.63,657.29 641.58,661.25
  region net GND: 641.61,1554.5 656.63,1549.94 670.47,1542.55 682.59,1532.59 692.55,1520.47 699.94,1506.63 704.5,1491.61 706.04,1476 704.5,1460.39 699.94,1445.37 692.55,1431.53 682.59,1419.41 670.47,1409.45 656.63,1402.06 641.61,1397.5 626,1395.96 610.39,1397.5 595.37,1402.06 581.53,1409.45 569.41,1419.41 559.45,1431.53 552.06,1445.37 547.5,1460.39 545.96,1476 547.5,1491.61 552.06,1506.63 559.45,1520.47 569.41,1532.59 581.53,1542.55 595.37,1549.94 610.39,1554.5 626,1556.04 hole: 628,1546.59 614.42,1545.25 601.37,1541.29 589.34,1534.86 578.8,1526.2 570.14,1515.66 563.71,1503.63 559.75,1490.58 558.41,1477 559.75,1463.42 563.71,1450.37 570.14,1438.34 578.8,1427.8 589.34,1419.14 601.37,1412.71 614.42,1408.75 628,1407.41 641.58,1408.75 654.63,1412.71 666.66,1419.14 677.2,1427.8 685.86,1438.34 692.29,1450.37 696.25,1463.42 697.59,1477 696.25,1490.58 692.29,1503.63 685.86,1515.66 677.2,1526.2 666.66,1534.86 654.63,1541.29 641.58,1545.25
  region net NetJ1_15: 1527.61,671.5 1542.63,666.94 1556.47,659.55 1568.59,649.59 1578.55,637.47 1585.94,623.63 1590.5,608.61 1592.04,593 1590.5,577.39 1585.94,562.37 1578.55,548.53 1568.59,536.41 1556.47,526.45 1542.63,519.06 1527.61,514.5 1512,512.96 1496.39,514.5 1481.37,519.06 1467.53,526.45 1455.41,536.41 1445.45,548.53 1438.06,562.37 1433.5,577.39 1431.96,593 1433.5,608.61 1438.06,623.63 1445.45,637.47 1455.41,649.59 1467.53,659.55 1481.37,666.94 1496.39,671.5 1512,673.04 hole: 1512,662.59 1498.42,661.25 1485.37,657.29 1473.34,650.86 1462.8,642.2 1454.14,631.66 1447.71,619.63 1443.75,606.58 1442.41,593 1443.75,579.42 1447.71,566.37 1454.14,554.34 1462.8,543.8 1473.34,535.14 1485.37,528.71 1498.42,524.75 1512,523.41 1525.58,524.75 1538.63,528.71 1550.66,535.14 1561.2,543.8 1569.86,554.34 1576.29,566.37 1580.25,579.42 1581.59,593 1580.25,606.58 1576.29,619.63 1569.86,631.66 1561.2,642.2 1550.66,650.86 1538.63,657.29 1525.58,661.25
  region net NetJ1_15: 1527.61,671.5 1542.63,666.94 1556.47,659.55 1568.59,649.59 1578.55,637.47 1585.94,623.63 1590.5,608.61 1592.04,593 1590.5,577.39 1585.94,562.37 1578.55,548.53 1568.59,536.41 1556.47,526.45 1542.63,519.06 1527.61,514.5 1512,512.96 1496.39,514.5 1481.37,519.06 1467.53,526.45 1455.41,536.41 1445.45,548.53 1438.06,562.37 1433.5,577.39 1431.96,593 1433.5,608.61 1438.06,623.63 1445.45,637.47 1455.41,649.59 1467.53,659.55 1481.37,666.94 1496.39,671.5 1512,673.04 hole: 1512,662.59 1498.42,661.25 1485.37,657.29 1473.34,650.86 1462.8,642.2 1454.14,631.66 1447.71,619.63 1443.75,606.58 1442.41,593 1443.75,579.42 1447.71,566.37 1454.14,554.34 1462.8,543.8 1473.34,535.14 1485.37,528.71 1498.42,524.75 1512,523.41 1525.58,524.75 1538.63,528.71 1550.66,535.14 1561.2,543.8 1569.86,554.34 1576.29,566.37 1580.25,579.42 1581.59,593 1580.25,606.58 1576.29,619.63 1569.86,631.66 1561.2,642.2 1550.66,650.86 1538.63,657.29 1525.58,661.25
Bottom Layer:
  rectangle net NetJ1_15: 1550,1266 1892,1366
  rectangle net NetJ1_13: 1544.03,1173 1892,1261
  region net SGND: 897,256 1132.5,256 1132.5,186.5 1139,186.5 1139,150.5 1128.04,149.43 1070,147.52 1011.96,149.43 954.16,155.12 896.86,164.58 840.3,177.76 784.73,194.62 730.38,215.08 721,219.33 721,256 887,256 887,287 897,287

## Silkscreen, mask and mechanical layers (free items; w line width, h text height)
Top Overlay:
  circle w10: c628,593 r90.15
  circle w10: c628,1477 r90.15
  circle w10: c1512,593 r90.15
Bottom Overlay:
  circle w10: c626,592 r90.15
  circle w10: c1510,592 r90.15
Mechanical 1:
  circle w5: c1512,1477 r64.25
  circle w5: c1512,593 r64.25
  circle w5: c628,593 r64.25
  circle w5: c628,1477 r64.25
  circle w5: c1070,1035 r900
